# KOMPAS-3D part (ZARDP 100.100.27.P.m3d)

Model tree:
1. Операция без истории:1
2. Операция без истории:2
3. Операция без истории:3
4. Операция без истории:4
5. Операция без истории:5
6. Операция без истории:6
7. Операция без истории:7
8. Операция без истории:8
9. Операция без истории:9
10. Операция без истории:10
11. Операция без истории:11
12. Операция без истории:12
13. Операция без истории:13
14. Операция без истории:14
15. Операция без истории:15
16. Операция без истории:16
17. Операция без истории:17
18. Операция без истории:18
19. Операция без истории:19
20. Операция без истории:20
21. Операция без истории:21
22. Операция без истории:22
23. Операция без истории:23
24. Операция без истории:24
25. Операция без истории:25
26. Операция без истории:26
27. Операция без истории:27
28. Операция без истории:28
29. Операция без истории:29
30. Операция без истории:30
31. Операция без истории:31
32. Операция без истории:32
33. Операция без истории:33
34. Операция без истории:34
35. Операция без истории:35
36. Операция без истории:36
37. Операция без истории:37
38. Операция без истории:38
39. Операция без истории:39
40. Операция без истории:40
41. Операция без истории:41
42. Операция без истории:42
43. Операция без истории:43
44. Операция без истории:44
45. Операция без истории:45
46. Операция без истории:46
47. Операция без истории:47
48. Операция без истории:48
49. Операция без истории:49
50. Операция без истории:50
51. Операция без истории:51
52. Операция без истории:52
53. Операция без истории:53
54. Операция без истории:54
55. Операция без истории:55
56. Операция без истории:56
57. Операция без истории:57
58. Операция без истории:58
59. Операция без истории:59
60. Операция без истории:60
61. Операция без истории:61
62. Операция без истории:62
63. Операция без истории:63
64. Операция без истории:64
65. Операция без истории:65
66. Операция без истории:66
67. Операция без истории:67
68. Операция без истории:68
69. Операция без истории:69
70. Операция без истории:70
71. Операция без истории:71
72. Операция без истории:72
73. Операция без истории:73
74. Операция без истории:74
75. Операция без истории:75
76. Операция без истории:76
77. Операция без истории:77
78. Операция без истории:78
79. Операция без истории:79
80. Операция без истории:80
81. Операция без истории:81
82. Операция без истории:82
83. Операция без истории:83
84. Операция без истории:84
85. Поверхность без истории:1
86. Поверхность без истории:2
87. Поверхность без истории:3
88. Поверхность без истории:4
89. Поверхность без истории:5
90. Поверхность без истории:6
91. Поверхность без истории:7
92. Поверхность без истории:8
93. Поверхность без истории:9
94. Поверхность без истории:10

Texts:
  ЗАРДП.100.100.27-XX.Р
